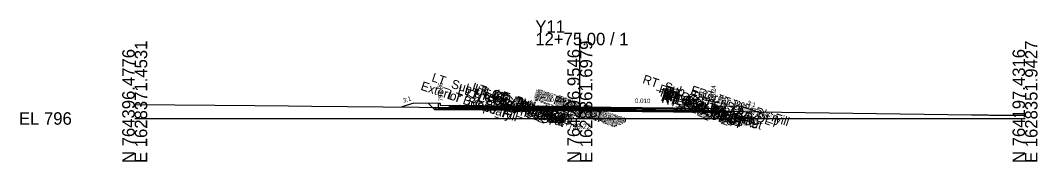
# Model space of a CAD drawing. Extents: x -26 to 203, y -10 to 6017.
# Drawn here: x -25.7 to 202.8, y 5490.3 to 5522 of the extents above; entities that cross this region are included whole.
import ezdxf

# ---------------------------------------------------------------- set-up
doc = ezdxf.new("R2010")
doc.units = 0
for name, color, linetype in [('Default', 7, 'Continuous'), ('Exist Cross Section Cell', 7, 'Continuous'), ('Exist XS Center Line Elevation Label', 7, 'Continuous'), ('Exist XS Ground Line', 7, 'Continuous'), ('Prop CMT Conc Surface', 7, 'Continuous'), ('Prop CMT Concrete Structures', 7, 'Continuous'), ('Prop CMT Pvmt Course 1', 7, 'Continuous'), ('Prop CMT Pvmt Course 1 CG', 7, 'Continuous'), ('Prop CMT Pvmt Course 2', 7, 'Continuous'), ('Prop CMT Pvmt Course 3', 7, 'Continuous'), ('Prop CMT Pvmt Surface', 7, 'Continuous'), ('Prop CMT Pvmt Wedge Surface 1', 7, 'Continuous'), ('Prop CMT Pvmt Wedge Surface 2', 7, 'Continuous'), ('Prop CMT Pvmt Wedge Surface 3', 7, 'Continuous'), ('Prop CMT Slope Grass', 7, 'Continuous'), ('Prop CMT Subgrade Earthwork', 7, 'Continuous'), ('Prop XS Hydro Elevations', 7, 'Continuous'), ('Prop XS SE Text', 7, 'Continuous'), ('Prop XS Side Slope Text', 7, 'Continuous'), ('Scratch_Level_0', 7, 'Continuous')]:
    doc.layers.add(name, color=color, linetype=linetype)

msp = doc.modelspace()

# ---------------------------------------------------------------- linework, layer by layer
at = {"layer": 'Exist Cross Section Cell'}
for p, q in [((100, 5500), (100, 5519.24)), ((0, 5500), (100, 5500)), ((100, 5500), (200, 5500))]:
    msp.add_line(p, q, dxfattribs=at)
at = {"layer": 'Exist XS Ground Line'}
msp.add_lwpolyline([(0, 5503.12), (26.95, 5502.92), (34.54, 5502.83), (39.72, 5502.79), (63.91, 5502.54), (89.92, 5502.34), (93.21, 5502.31), (97.9, 5502.25), (100, 5502.21), (134.01, 5501.66), (136.89, 5501.58), (139.97, 5501.49), (187.98, 5500.85), (189.91, 5500.82), (191.7, 5500.8), (192.04, 5500.78), (200, 5500.75)], dxfattribs=at)
at = {"layer": 'Prop CMT Conc Surface'}
for points in [[(68.68, 5502.85), (68.68, 5503.35), (68.18, 5503.35)], [(70.68, 5502.91), (68.68, 5502.85)], [(128, 5502.34), (130, 5502.24)], [(130, 5502.24), (130.01, 5502.74), (130.51, 5502.74)]]:
    msp.add_lwpolyline(points, dxfattribs=at)
at = {"layer": 'Prop CMT Concrete Structures'}
for points in [[(70.68, 5502.91), (68.68, 5502.85), (68.68, 5503.35), (68.18, 5503.35)], [(68.18, 5503.35), (68.18, 5502.35), (70.68, 5502.33)], [(70.68, 5502.33), (70.68, 5502.91)], [(128, 5502.34), (130, 5502.24), (130.01, 5502.74), (130.51, 5502.74)], [(130.51, 5502.74), (130.5, 5501.73), (128, 5501.75)], [(128, 5501.75), (128, 5502.34)]]:
    msp.add_lwpolyline(points, dxfattribs=at)
at = {"layer": 'Prop CMT Pvmt Course 1'}
for points in [[(100, 5502.62), (70.68, 5502.91)], [(70.68, 5502.91), (70.68, 5502.66)], [(70.68, 5502.66), (100, 5502.37)], [(100, 5502.37), (100, 5502.62)], [(100, 5502.62), (128, 5502.34)], [(100, 5502.37), (100, 5502.62)], [(128, 5502.09), (100, 5502.37)], [(128, 5502.34), (128, 5502.09)]]:
    msp.add_lwpolyline(points, dxfattribs=at)
msp.add_lwpolyline([(100, 5502.37), (100, 5502.49), (100, 5502.49), (100, 5502.37)], close=True, dxfattribs=at)
msp.add_lwpolyline([(100, 5502.37), (100, 5502.49), (100, 5502.49), (100, 5502.37)], close=True, dxfattribs=at)
at = {"layer": 'Prop CMT Pvmt Course 1 CG'}
for points in [[(70.68, 5502.33), (67.68, 5502.36), (67.35, 5502.03)], [(67.35, 5502.03), (70.68, 5501.99)], [(70.68, 5501.99), (70.68, 5502.33)], [(128, 5501.75), (131, 5501.72), (131.34, 5501.39)], [(128, 5501.42), (128, 5501.75)], [(131.34, 5501.39), (128, 5501.42)]]:
    msp.add_lwpolyline(points, dxfattribs=at)
at = {"layer": 'Prop CMT Pvmt Course 2'}
for points in [[(100, 5502.37), (70.68, 5502.66)], [(70.68, 5502.66), (70.68, 5502.33)], [(70.68, 5502.33), (100, 5502.03)], [(100, 5502.03), (100, 5502.37)], [(100, 5502.03), (100, 5502.37)], [(100, 5502.37), (128, 5502.09)], [(100, 5502.37), (100, 5502.37)], [(100, 5502.37), (100, 5502.37)], [(128, 5501.75), (100, 5502.03)], [(128, 5502.09), (128, 5501.75)]]:
    msp.add_lwpolyline(points, dxfattribs=at)
msp.add_lwpolyline([(100, 5502.37), (100, 5502.03), (100, 5502.03)], close=True, dxfattribs=at)
msp.add_lwpolyline([(100, 5502.37), (100, 5502.03), (100, 5502.03)], close=True, dxfattribs=at)
at = {"layer": 'Prop CMT Pvmt Course 3'}
for points in [[(100, 5502.03), (70.68, 5502.33)], [(70.68, 5502.33), (70.68, 5501.99)], [(70.68, 5501.99), (100, 5501.7)], [(100, 5501.7), (100, 5502.03)], [(100, 5502.03), (128, 5501.75)], [(100, 5501.7), (100, 5502.03)], [(100, 5502.03), (100, 5502.03), (100, 5501.7), (100, 5501.7)], [(100, 5501.7), (100, 5502.03)], [(100, 5502.03), (100, 5502.03), (100, 5501.7), (100, 5501.7)], [(100, 5501.7), (100, 5502.03)], [(128, 5501.42), (100, 5501.7)], [(128, 5501.75), (128, 5501.42)]]:
    msp.add_lwpolyline(points, dxfattribs=at)
at = {"layer": 'Prop CMT Pvmt Surface'}
for points in [[(100, 5502.62), (70.68, 5502.91)], [(100, 5502.62), (128, 5502.34)]]:
    msp.add_lwpolyline(points, dxfattribs=at)
at = {"layer": 'Prop CMT Pvmt Wedge Surface 1'}
for points in [[(100, 5502.62), (100, 5502.37), (100, 5502.37)], [(100, 5502.62), (100, 5502.37), (100, 5502.37)], [(100, 5502.37), (100, 5502.49)], [(100, 5502.37), (100, 5502.49)]]:
    msp.add_lwpolyline(points, dxfattribs=at)
at = {"layer": 'Prop CMT Pvmt Wedge Surface 2'}
for points in [[(100, 5502.62), (100, 5502.37)], [(100, 5502.62), (100, 5502.37)], [(100, 5502.37), (100, 5502.37)], [(100, 5502.37), (100, 5502.37)]]:
    msp.add_lwpolyline(points, dxfattribs=at)
at = {"layer": 'Prop CMT Pvmt Wedge Surface 3'}
for points in [[(100, 5502.62), (100, 5502.03)], [(100, 5502.62), (100, 5502.03)], [(100, 5502.03), (100, 5502.03)], [(100, 5502.03), (100, 5502.03)]]:
    msp.add_lwpolyline(points, dxfattribs=at)
at = {"layer": 'Prop CMT Slope Grass'}
for points in [[(68.18, 5503.35), (62.68, 5503.46), (60.04, 5502.58)], [(130.51, 5502.74), (136.01, 5502.85), (140.09, 5501.49)]]:
    msp.add_lwpolyline(points, dxfattribs=at)
at = {"layer": 'Prop CMT Subgrade Earthwork'}
for points in [[(70.68, 5501.99), (67.35, 5502.03), (65.99, 5503.39)], [(100, 5501.7), (70.68, 5501.99)], [(100, 5501.7), (128, 5501.42)], [(128, 5501.42), (131.34, 5501.39), (132.74, 5502.78)]]:
    msp.add_lwpolyline(points, dxfattribs=at)

# ---------------------------------------------------------------- texts
at = {"layer": 'Default'}
msp.add_text('-', height=0.0001, dxfattribs=at).set_placement((0, 5500))
at = {"layer": 'Exist Cross Section Cell'}
for s, p in [('Y11', (90, 5519.24)), ('12+75.00 / 1', (90, 5516.44)), ('EL 796', (-26, 5498.6))]:
    msp.add_text(s, height=2.8, dxfattribs=at).set_placement(p)
for s, p in [('E 1628371.4531', (2.8, 5490)), ('E 1628361.6979', (102.8, 5490)), ('E 1628351.9427', (202.8, 5490)), ('N 764396.4776', (0, 5490)), ('N 764296.9546', (100, 5490)), ('N 764197.4316', (200, 5490))]:
    msp.add_text(s, height=2.8, rotation=90, dxfattribs=at).set_placement(p)
at = {"layer": 'Exist XS Center Line Elevation Label'}
msp.add_text('798.22', height=1.2, dxfattribs=at).set_placement((97.41, 5497.62))
at = {"layer": 'Prop XS Hydro Elevations'}
for s, p in [('798.86', (69.18, 5503.85)), ('798.24', (130.5, 5503.24))]:
    msp.add_text(s, height=1, rotation=90, dxfattribs=at).set_placement(p)
at = {"layer": 'Prop XS SE Text'}
for p in [(93.38, 5503.68), (112.38, 5503.49)]:
    msp.add_text('0.010', height=1, rotation=359.4271, dxfattribs=at).set_placement(p)
at = {"layer": 'Prop XS Side Slope Text'}
for rotation, p in [(18.4332, (60.42, 5503.5)), (341.5668, (137.53, 5503.13))]:
    msp.add_text('3:1', height=1, rotation=rotation, dxfattribs=at).set_placement(p)
at = {"layer": 'Scratch_Level_0'}
for s, p in [('LT_Sub_Trench_Out_DLT', (66.55, 5508.4)), ('Exterior Boundary', (64.1, 5506.49)), ('LT_CG_Top_Face', (75.6, 5506.24)), ('LT_CG_Top_BOC', (76.07, 5505.91)), ('RT_Sub_Trench_Out_DLT', (113.94, 5507.99)), ('RT_CG_Top_Face', (117.56, 5505.83)), ('LT_Slope_Fill', (70.15, 5504.47)), ('LT_CSLP_Pnt', (72.36, 5505.42)), ('LT_CG1_Shelf_Out', (73.93, 5505.47)), ('LT_CG_Bot_BOC', (76.1, 5504.9)), ('LT_CG_Top_Gut', (76.52, 5505.43)), ('LT_Sub_OEOP', (76.97, 5504.01)), ('LT_CG_Bot_IE', (80.11, 5504.37)), ('LT_Sub_OEOT', (80.27, 5503.99)), ('LT_PV2_OEOT', (80.36, 5504.62)), ('LT_PV3_OEOT', (80.36, 5504.29)), ('LT_PV1_OEOT', (80.9, 5504.7)), ('RT_Sub_OEEOP', (89.41, 5504.18)), ('LT_Sub_OEEOP', (89.45, 5504.16)), ('RT_PV2_OEEOP', (89.49, 5504.81)), ('RT_PV3_OEEOP', (89.49, 5504.48)), ('LT_PV2_OEEOP', (89.54, 5504.8)), ('LT_PV3_OEEOP', (89.54, 5504.47)), ('RT_Sub_IEEOP', (90.02, 5503.97)), ('RT_PV1_OEEOP', (90.03, 5504.76)), ('LT_Sub_IEEOP', (90.06, 5503.96)), ('LT_PV1_OEEOP', (90.08, 5504.74)), ('RT_PV2_IEEOP', (90.11, 5504.61)), ('RT_PV3_IEEOP', (90.11, 5504.28)), ('LT_PV2_IEEOP', (90.15, 5504.59)), ('LT_PV3_IEEOP', (90.15, 5504.26)), ('RT_PV1_IEEOP', (90.65, 5504.56)), ('LT_PV1_IEEOP', (90.69, 5504.54)), ('RT_CG1_Shelf_Out', (117.88, 5505.04)), ('RT_CG_Bot_IE', (118.07, 5504.01)), ('RT_Sub_OEOT', (118.23, 5503.62)), ('RT_PV2_OEOT', (118.32, 5504.26)), ('RT_PV3_OEOT', (118.32, 5503.93)), ('RT_CG_Top_Gut', (118.48, 5505.02)), ('RT_PV1_OEOT', (118.86, 5504.33)), ('RT_CG_Top_BOC', (119.03, 5505.51)), ('RT_CG_Bot_BOC', (119.06, 5504.49)), ('RT_Sub_OEOP', (121.6, 5503.58)), ('Exterior Boundary', (124.72, 5505.55)), ('RT_CSLP_Pnt', (126.32, 5505.02)), ('RT_Slope_Fill', (130.73, 5503.55)), ('Sub_PGL', (93.81, 5502.71)), ('PV2_PGL', (93.9, 5503.34)), ('PV3_PGL', (93.9, 5503.01)), ('PV1_PGL', (94.44, 5503.42))]:
    msp.add_text(s, height=2, rotation=341.5651, dxfattribs=at).set_placement(p)

doc.saveas('drawing.dxf')
